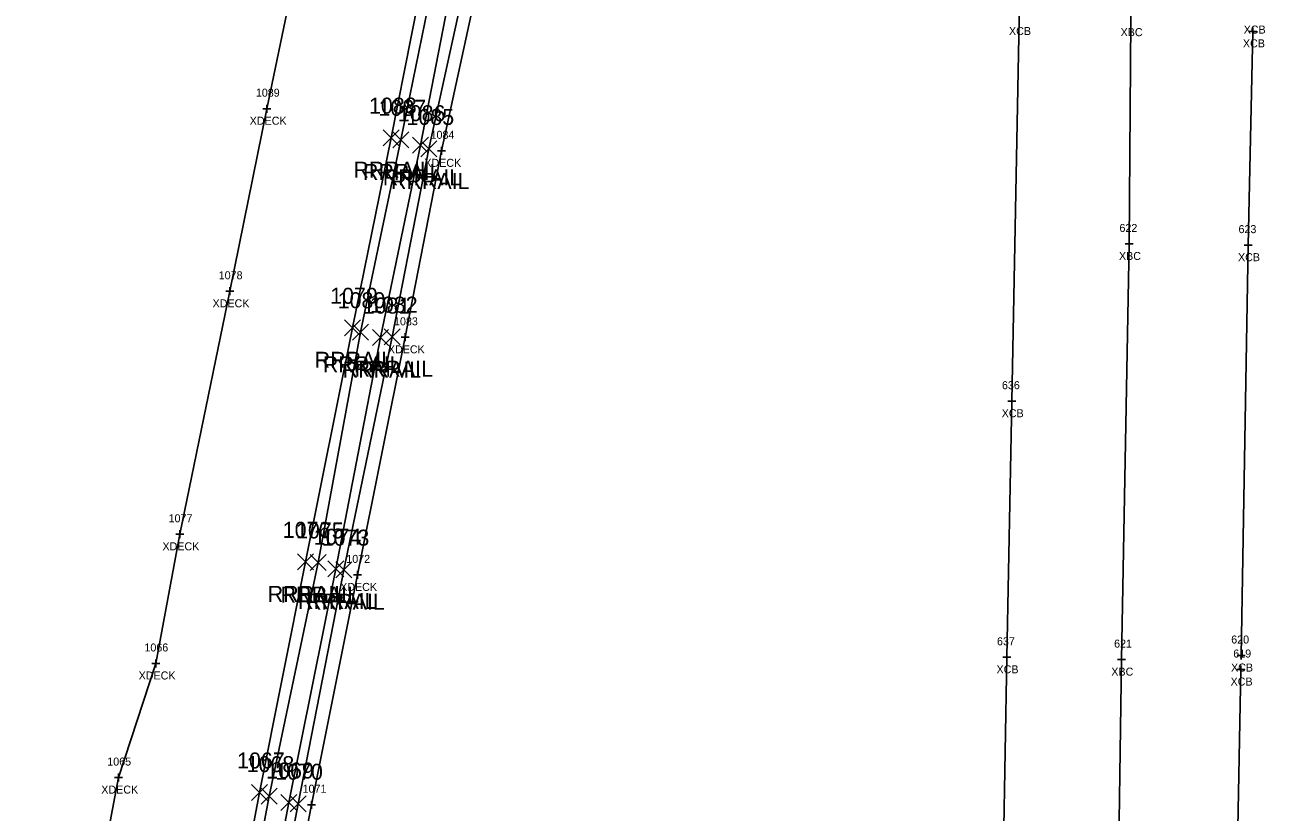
# Model space of a CAD drawing. Extents: x 1715662 to 1717487, y 887396 to 890004.
# Drawn here: x 1716478.4 to 1716633.4, y 888500.3 to 888598.7 of the extents above; entities that cross this region are included whole.
import ezdxf

# ---------------------------------------------------------------- set-up
doc = ezdxf.new("R2010")
doc.units = 0
for name, color, linetype in [('B_A', 7, 'Continuous'), ('B_I', 7, 'Continuous'), ('B_TIC', 7, 'Continuous'), ('BDC', 7, 'Continuous'), ('BELB', 7, 'Continuous'), ('R_A', 7, 'Continuous'), ('R_I', 7, 'Continuous'), ('R_TIC', 7, 'Continuous'), ('RR', 7, 'Continuous')]:
    doc.layers.add(name, color=color, linetype=linetype)

msp = doc.modelspace()

# ---------------------------------------------------------------- linework, layer by layer
at = {"layer": 'B_TIC'}
for p, q in [((1716631.84, 888597.84), (1716631.91, 888597.84)), ((1716508.66, 888588.18), (1716508.74, 888588.18)), ((1716530.47, 888582.92), (1716530.55, 888582.92)), ((1716616.36, 888571.29), (1716616.43, 888571.29)), ((1716631.23, 888571.14), (1716631.31, 888571.14)), ((1716504.02, 888565.38), (1716504.1, 888565.38)), ((1716525.92, 888559.63), (1716525.99, 888559.63)), ((1716601.7, 888551.65), (1716601.78, 888551.65)), ((1716497.76, 888535.03), (1716497.84, 888535.03)), ((1716519.96, 888529.96), (1716520.04, 888529.96)), ((1716630.36, 888519.89), (1716630.43, 888519.89)), ((1716494.79, 888518.9), (1716494.86, 888518.9)), ((1716601.06, 888519.67), (1716601.14, 888519.67)), ((1716615.4, 888519.38), (1716615.48, 888519.38)), ((1716630.3, 888518.14), (1716630.38, 888518.14)), ((1716490.12, 888504.65), (1716490.19, 888504.65)), ((1716514.22, 888501.26), (1716514.29, 888501.26))]:
    msp.add_line(p, q, dxfattribs=at)
for points in [[(1716631.33, 888597.84), (1716632.33, 888597.84)], [(1716631.83, 888597.34), (1716631.83, 888598.34)], [(1716508.16, 888588.18), (1716509.16, 888588.18)], [(1716508.66, 888587.68), (1716508.66, 888588.68)], [(1716530.47, 888582.42), (1716530.47, 888583.42)], [(1716529.97, 888582.92), (1716530.97, 888582.92)], [(1716615.86, 888571.29), (1716616.86, 888571.29)], [(1716616.36, 888570.79), (1716616.36, 888571.79)], [(1716630.73, 888571.14), (1716631.73, 888571.14)], [(1716631.23, 888570.64), (1716631.23, 888571.64)], [(1716503.52, 888565.38), (1716504.52, 888565.38)], [(1716504.02, 888564.88), (1716504.02, 888565.88)], [(1716525.91, 888559.13), (1716525.91, 888560.13)], [(1716525.41, 888559.63), (1716526.41, 888559.63)], [(1716601.2, 888551.65), (1716602.2, 888551.65)], [(1716601.7, 888551.15), (1716601.7, 888552.15)], [(1716497.76, 888534.53), (1716497.76, 888535.53)], [(1716497.26, 888535.03), (1716498.26, 888535.03)], [(1716519.46, 888529.96), (1716520.46, 888529.96)], [(1716519.96, 888529.46), (1716519.96, 888530.46)], [(1716601.06, 888519.17), (1716601.06, 888520.17)], [(1716615.4, 888518.88), (1716615.4, 888519.88)], [(1716629.85, 888519.89), (1716630.85, 888519.89)], [(1716630.35, 888519.39), (1716630.35, 888520.39)], [(1716494.28, 888518.9), (1716495.28, 888518.9)], [(1716494.78, 888518.4), (1716494.78, 888519.4)], [(1716600.56, 888519.67), (1716601.56, 888519.67)], [(1716614.9, 888519.38), (1716615.9, 888519.38)], [(1716629.8, 888518.14), (1716630.8, 888518.14)], [(1716630.3, 888517.64), (1716630.3, 888518.64)], [(1716489.62, 888504.65), (1716490.62, 888504.65)], [(1716490.12, 888504.15), (1716490.12, 888505.15)], [(1716513.71, 888501.26), (1716514.71, 888501.26)], [(1716514.21, 888500.76), (1716514.21, 888501.76)]]:
    msp.add_lwpolyline(points, dxfattribs=at)
at = {"layer": 'BDC'}
for points in [[(1716604.08, 888679.35), (1716603.37, 888635.79), (1716602.62, 888599.38), (1716601.7, 888551.65), (1716601.06, 888519.67), (1716600.26, 888472.39), (1716599.73, 888439.67), (1716598.79, 888390.75), (1716598.29, 888359.77)], [(1716630.35, 888519.89), (1716631.23, 888571.14), (1716631.83, 888597.84)], [(1716628.94, 888440.09), (1716629.71, 888487.4), (1716630.3, 888518.14)]]:
    msp.add_lwpolyline(points, dxfattribs=at)
at = {"layer": 'BELB'}
for points in [[(1716478.41, 888445.68), (1716503.08, 888441.52), (1716508.07, 888469.67), (1716514.21, 888501.26), (1716519.96, 888529.96), (1716525.91, 888559.63), (1716530.47, 888582.92), (1716536.26, 888609.51), (1716540.95, 888632.35), (1716545.99, 888655.48), (1716550.79, 888676.28), (1716540.9, 888678.16), (1716542.76, 888686.4), (1716535.06, 888687.95)], [(1716478.41, 888445.68), (1716484.44, 888474.77), (1716490.12, 888504.65), (1716494.78, 888518.9), (1716497.76, 888535.03), (1716504.02, 888565.38), (1716508.66, 888588.18), (1716513.89, 888613.4), (1716518.93, 888636.07), (1716523.44, 888635.06), (1716528.82, 888659.7), (1716535.06, 888687.95)], [(1716612.85, 888359.68), (1716613.89, 888403.99), (1716614.37, 888439.47), (1716614.94, 888487.77), (1716615.4, 888519.38), (1716616.36, 888571.29), (1716616.55, 888599.24), (1716617.56, 888647.27), (1716618.08, 888679.12)]]:
    msp.add_lwpolyline(points, dxfattribs=at)
at = {"layer": 'R_TIC'}
for points in [[(1716523.17, 888583.56), (1716525.17, 888585.56)], [(1716525.17, 888583.56), (1716523.17, 888585.56)], [(1716524.36, 888583.29), (1716526.36, 888585.29)], [(1716526.36, 888583.29), (1716524.36, 888585.29)], [(1716526.83, 888582.61), (1716528.83, 888584.61)], [(1716528.83, 888582.61), (1716526.83, 888584.61)], [(1716527.86, 888582.15), (1716529.86, 888584.15)], [(1716529.86, 888582.15), (1716527.86, 888584.15)], [(1716518.33, 888559.82), (1716520.33, 888561.82)], [(1716520.33, 888559.82), (1716518.33, 888561.82)], [(1716519.35, 888559.26), (1716521.35, 888561.26)], [(1716521.35, 888559.26), (1716519.35, 888561.26)], [(1716521.82, 888558.59), (1716523.82, 888560.59)], [(1716523.82, 888558.59), (1716521.82, 888560.59)], [(1716523.3, 888558.71), (1716525.3, 888560.71)], [(1716525.3, 888558.71), (1716523.3, 888560.71)], [(1716512.46, 888530.59), (1716514.46, 888532.59)], [(1716514.46, 888530.59), (1716512.46, 888532.59)], [(1716514.06, 888530.51), (1716516.06, 888532.51)], [(1716516.06, 888530.51), (1716514.06, 888532.51)], [(1716516.25, 888529.72), (1716518.25, 888531.72)], [(1716518.25, 888529.72), (1716516.25, 888531.72)], [(1716517.26, 888529.61), (1716519.26, 888531.61)], [(1716519.26, 888529.61), (1716517.26, 888531.61)], [(1716506.74, 888501.79), (1716508.74, 888503.79)], [(1716508.74, 888501.79), (1716506.74, 888503.79)], [(1716507.93, 888501.33), (1716509.93, 888503.33)], [(1716509.93, 888501.33), (1716507.93, 888503.33)], [(1716510.38, 888500.53), (1716512.38, 888502.53)], [(1716512.38, 888500.53), (1716510.38, 888502.53)], [(1716511.55, 888500.38), (1716513.55, 888502.38)], [(1716513.55, 888500.38), (1716511.55, 888502.38)]]:
    msp.add_lwpolyline(points, dxfattribs=at)
at = {"layer": 'RR'}
for points in [[(1716487.31, 888387.93), (1716492.21, 888417.1), (1716496.28, 888440.7), (1716501.72, 888471.07), (1716507.74, 888502.79), (1716513.46, 888531.59), (1716519.33, 888560.82), (1716524.17, 888584.56), (1716529.26, 888610.21), (1716534.8, 888633.88), (1716539.7, 888657.28), (1716544.48, 888678.15), (1716548.86, 888696.72), (1716554.01, 888719.92)], [(1716492.09, 888386.99), (1716497, 888416.35), (1716500.91, 888439.31), (1716506.48, 888469.5), (1716512.55, 888501.38), (1716518.26, 888530.61), (1716524.3, 888559.71), (1716528.86, 888583.15), (1716534.49, 888608.85), (1716539.41, 888632.6), (1716544.59, 888655.95), (1716549.42, 888676.86), (1716553.66, 888695.32), (1716558.99, 888718.88)], [(1716494.39, 888416.83), (1716494.94, 888422.88), (1716498.1, 888442.46), (1716502.94, 888470.67), (1716508.93, 888502.33), (1716515.06, 888531.51), (1716520.35, 888560.26), (1716525.36, 888584.29), (1716530.64, 888609.99), (1716535.75, 888633.48), (1716541.02, 888656.86), (1716546.22, 888677.74), (1716550.45, 888696.31), (1716552.41, 888702.12)], [(1716494.74, 888416.93), (1716496.25, 888422.64), (1716499.96, 888442.36), (1716505.26, 888469.46), (1716511.38, 888501.53), (1716517.25, 888530.72), (1716522.82, 888559.59), (1716527.83, 888583.61), (1716532.88, 888609.62), (1716538.44, 888633.19), (1716543.26, 888656.01), (1716547.79, 888677.36), (1716551.88, 888695.51), (1716552.71, 888701.89)]]:
    msp.add_lwpolyline(points, dxfattribs=at)

# ---------------------------------------------------------------- texts
at = {"layer": 'B_A'}
for s, p in [('XCB', (1716601.35, 888597.38)), ('XBC', (1716615.29, 888597.24)), ('XCB', (1716630.67, 888597.56)), ('XCB', (1716630.57, 888595.84)), ('XDECK', (1716506.5, 888586.18)), ('XDECK', (1716528.31, 888580.92)), ('XBC', (1716615.09, 888569.29)), ('XCB', (1716629.96, 888569.14)), ('XDECK', (1716501.86, 888563.38)), ('XDECK', (1716523.76, 888557.63)), ('XCB', (1716600.44, 888549.65)), ('XDECK', (1716495.6, 888533.03)), ('XDECK', (1716517.8, 888527.96)), ('XCB', (1716599.79, 888517.67)), ('XBC', (1716614.13, 888517.38)), ('XCB', (1716629.09, 888517.89)), ('XDECK', (1716492.63, 888516.9)), ('XCB', (1716629.03, 888516.14)), ('XDECK', (1716487.96, 888502.65))]:
    msp.add_text(s, height=1, dxfattribs=at).set_placement(p)
at = {"layer": 'B_I'}
for s, p in [('1089', (1716507.27, 888589.68)), ('1084', (1716529.09, 888584.42)), ('622', (1716615.15, 888572.79)), ('623', (1716630.02, 888572.64)), ('1078', (1716502.63, 888566.88)), ('1083', (1716524.53, 888561.13)), ('636', (1716600.47, 888553.15)), ('1077', (1716496.37, 888536.53)), ('1072', (1716518.57, 888531.46)), ('1066', (1716493.35, 888520.4)), ('637', (1716599.85, 888521.17)), ('621', (1716614.48, 888520.88)), ('620', (1716629.11, 888521.39)), ('619', (1716629.37, 888519.64)), ('1065', (1716488.71, 888506.15)), ('1071', (1716513.11, 888502.76))]:
    msp.add_text(s, height=1, dxfattribs=at).set_placement(p)
at = {"layer": 'R_A'}
for p in [(1716519.46, 888579.56), (1716520.65, 888579.29), (1716523.12, 888578.61), (1716524.15, 888578.15), (1716514.62, 888555.82), (1716515.64, 888555.26), (1716518.11, 888554.59), (1716519.59, 888554.71), (1716508.75, 888526.59), (1716510.35, 888526.51), (1716512.54, 888525.72), (1716513.56, 888525.61)]:
    msp.add_text('RRRAIL', height=2, dxfattribs=at).set_placement(p)
at = {"layer": 'R_I'}
for s, p in [('1088', (1716521.4, 888587.56)), ('1087', (1716522.59, 888587.29)), ('1086', (1716525, 888586.61)), ('1085', (1716526.09, 888586.15)), ('1079', (1716516.55, 888563.82)), ('1080', (1716517.49, 888563.26)), ('1082', (1716521.53, 888562.71)), ('1081', (1716520.62, 888562.59)), ('1076', (1716510.63, 888534.59)), ('1075', (1716512.29, 888534.51)), ('1074', (1716514.48, 888533.72)), ('1073', (1716515.49, 888533.61)), ('1067', (1716504.92, 888505.79)), ('1068', (1716506.12, 888505.33)), ('1069', (1716508.56, 888504.53)), ('1070', (1716509.69, 888504.38))]:
    msp.add_text(s, height=2, dxfattribs=at).set_placement(p)

doc.saveas('drawing.dxf')
